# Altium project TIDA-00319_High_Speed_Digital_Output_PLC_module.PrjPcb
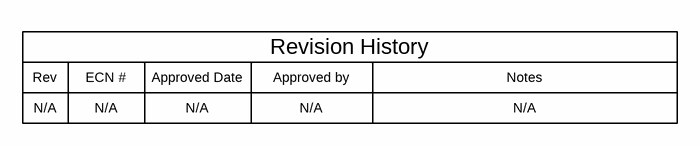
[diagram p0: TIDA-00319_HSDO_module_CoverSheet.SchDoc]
TID: TIDA-00319; TechSupport: http://www.ti.com/support; SCH_Rev: E1; PRJ_Title: High Speed Digital Output Module for PLC; PRJ_Number: TIDA-00319; PRJ_Engineer: Ahmed Noeman; PRJ_Customer: Public Release; PCB_Rev: E1; PCB_Layout: Ahmed Noeman; CopyrightYear: 2016
6 sheets, 93 parts. Net scope: global (net labels, ports and power ports of the same name join across sheets).
Board file: TIDA-00319_HSDO_module.PcbDoc
Sheets:
  TIDA-00319_HSDO_module_CoverSheet.SchDoc
  TIDA-00319_HSDO_module_Hardware.SchDoc
  TIDA-00319_HSDO_module_BBB_connector.SchDoc
  TIDA-00319_HSDO_module_power.SchDoc
  TIDA-00319_HSDO_module_isolation.SchDoc
  TIDA-00319_HSDO_module_singout.SchDoc

## Sheet TIDA-00319_HSDO_module_CoverSheet.SchDoc
size 431 x 279 mm; Date: Not shown in title block; ApprovedBy: Not shown in title block; CheckedBy: Not shown in title block; Author: Not shown in title block; CompanyName: Not shown in title block; DrawnBy: Ahmed Noeman; Engineer: Ahmed Noeman; Organization: Not shown in title block; Address1: Not shown in title block; Address2: Not shown in title block; Address3: Not shown in title block; Address4: Not shown in title block; DocumentNumber: 1; Revision: Use project parameter SCH_Rev; SheetNumber: 1; SheetTotal: 3; PageSetup: Record=PageOptions¦CenterHorizontal=True¦CenterVertical=True¦PrintScale=1.00¦XCorrection=1.00¦YCorrection=1.00¦PrintKind=0¦BorderSize=5000000¦LeftOffset=0¦BottomOffset=0¦Orientation=2¦PaperLength=1000¦PaperWidth=1000¦Scale=100¦PaperSource=15¦PrintQuality=600¦MediaType=1¦DitherType=10¦PaperKind=Letter¦PrintScaleMode=1

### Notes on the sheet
- Rev
- N/A
- ECN #
- Approved Date
- Approved by
- Revision History
- Notes

## Sheet TIDA-00319_HSDO_module_Hardware.SchDoc
size 431 x 279 mm; Date: Not shown in title block; ApprovedBy: Not shown in title block; CheckedBy: Not shown in title block; Author: Not shown in title block; CompanyName: Not shown in title block; DrawnBy: Ahmed Noeman; Engineer: Ahmed Noeman; Organization: Not shown in title block; Address1: Not shown in title block; Address2: Not shown in title block; Address3: Not shown in title block; Address4: Not shown in title block; DocumentNumber: 1; Revision: Use project parameter SCH_Rev; SheetNumber: 2; SheetTotal: 3; PageSetup: Record=PageOptions¦CenterHorizontal=True¦CenterVertical=True¦PrintScale=1.00¦XCorrection=1.00¦YCorrection=1.00¦PrintKind=0¦BorderSize=5000000¦LeftOffset=0¦BottomOffset=0¦Orientation=2¦PaperLength=1000¦PaperWidth=1000¦Scale=100¦PaperSource=15¦PrintQuality=600¦MediaType=1¦DitherType=10¦PaperKind=Letter¦PrintScaleMode=1
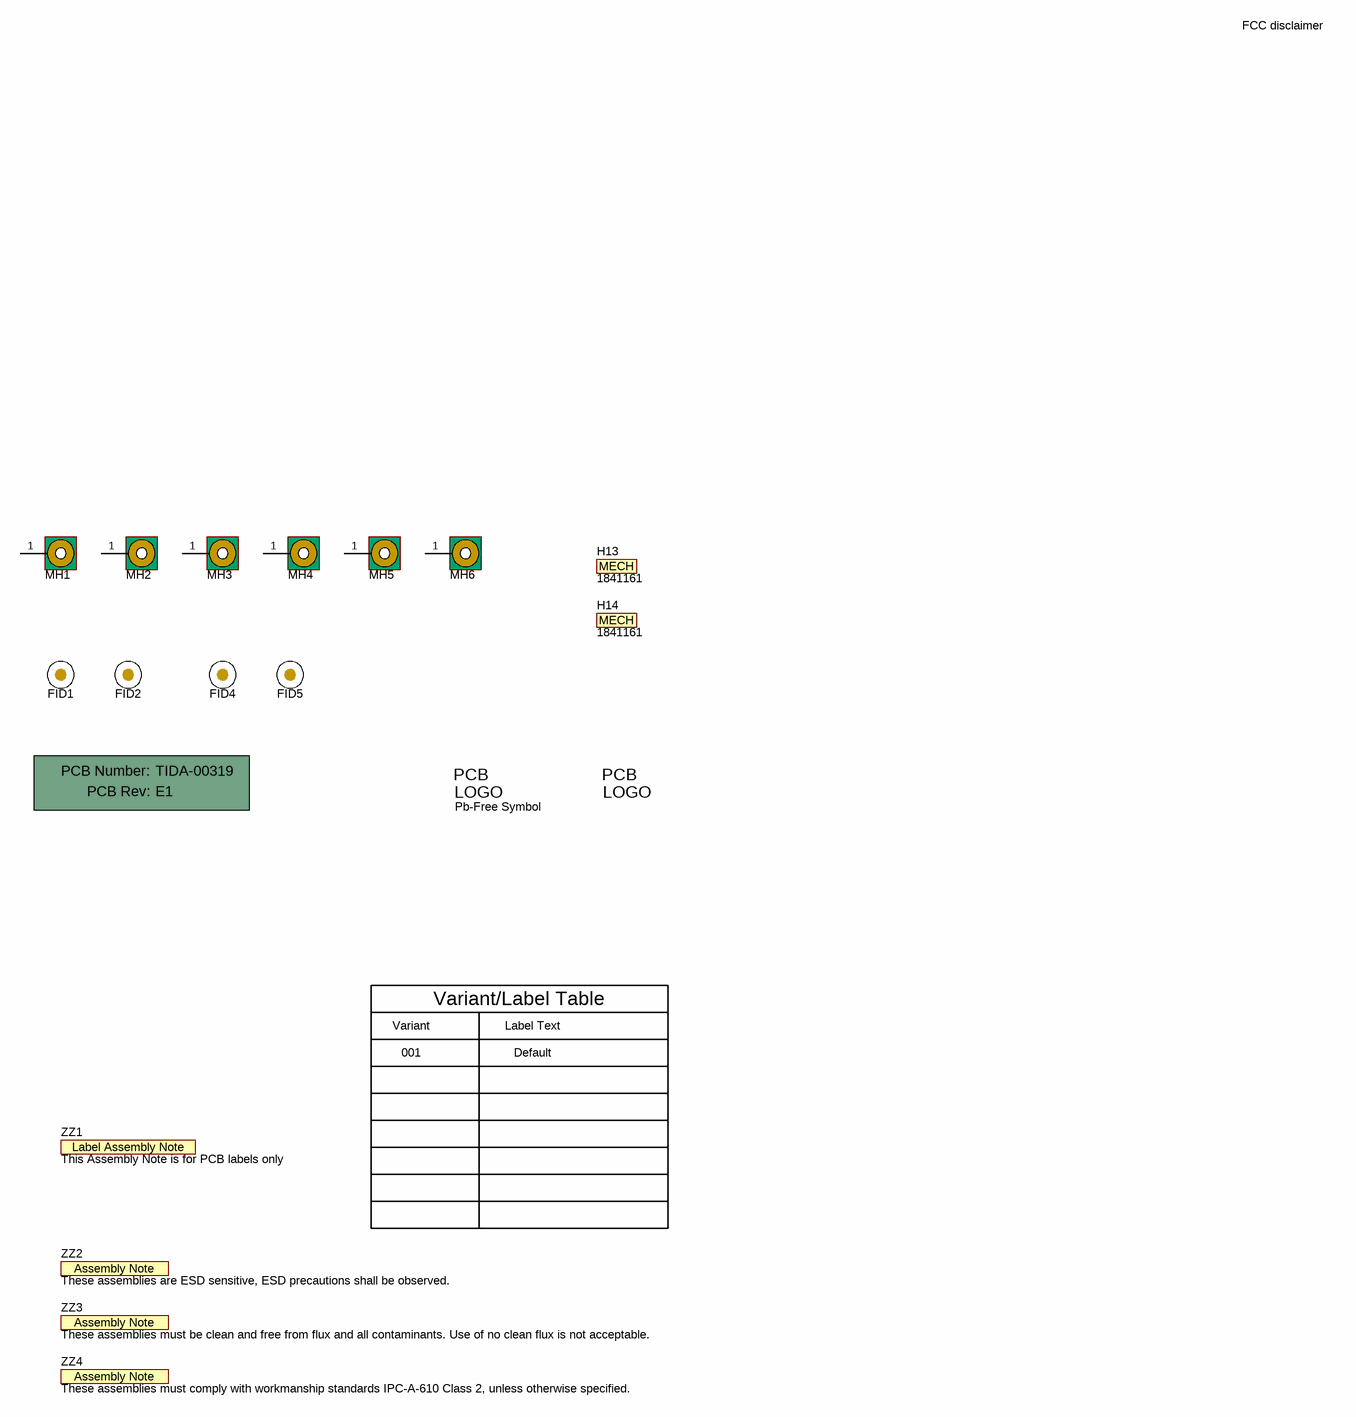
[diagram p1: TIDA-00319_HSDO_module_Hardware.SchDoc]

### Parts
!PCB1  Printed Circuit Board  (value not drawn)  (mechanical)
FID1  Fiducial  [Fiducial10-20]  (value not drawn)
FID2  Fiducial  [Fiducial10-20]  (value not drawn)
FID4  Fiducial  [Fiducial10-20]  (value not drawn)
FID5  Fiducial  [Fiducial10-20]  (value not drawn)
H13  1841161  (mechanical)
H14  1841161  (mechanical)
Logo2  Pb-Free Symbol  [Pb-Free_Overlay_Small]  (no BOM)
Logo3  FCC disclaimer  [FCC_disclaimer_stacked]  (no BOM)
MH1  MTG_Pads  [MTGP_4-40_PanHead]  (value not drawn)  (no BOM)
MH2  MTG_Pads  [MTGP_4-40_PanHead]  (value not drawn)  (no BOM)
MH3  MTG_Pads  [MTGP_4-40_PanHead]  (value not drawn)  (no BOM)
MH4  MTG_Pads  [MTGP_4-40_PanHead]  (value not drawn)  (no BOM)
MH5  MTG_Pads  [MTGP_4-40_PanHead]  (value not drawn)  (no BOM)
MH6  MTG_Pads  [MTGP_4-40_PanHead]  (value not drawn)  (no BOM)
ZZ1  This Assembly Note is for PCB labels only  [AssemblyNoteLabel]  (no BOM)
ZZ2  These assemblies are ESD sensitive, ESD precautions shall be observed.  [AssemblyNote]  (no BOM)
ZZ3  These assemblies must be clean and free from flux and all contaminants. Use of no clean flux is not acceptable.  [AssemblyNote]  (no BOM)
ZZ4  These assemblies must comply with workmanship standards IPC-A-610 Class 2, unless otherwise specified.  [AssemblyNote]  (no BOM)

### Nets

Not connected (* = marked no-connect by the designer): MH1 1; MH2 1; MH3 1; MH4 1; MH5 1; MH6 1

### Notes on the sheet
- Variant
- Variant/Label Table
- Label Text
- 001
- Default

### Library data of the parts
!PCB1 = PCB: Manufacturer: Any; PartNumber: TIDA-00319; SymbolCreator: a0412235
FID1 FID2 FID4 FID5 = Fiducial: Fiducial mark.  There is nothing to buy or mount.; SymbolCreator: codlsc
H13 H14 = 1841161: Fiber optics - MC 1,5/10-LWL 1,5-3,5 for Phoenix connectors; Manufacturer: Phoenix Contact; SymbolCreator: codlsc; CompType: Filber Optics
Logo2 = Pb-Free: SymbolCreator: a0412235
Logo3 = FCC_disclaimer: SymbolCreator: a0412235
MH1-MH6 = Mounting Hole (Imperial) with Pads: PCB Mounting Hole; Manufacturer: Any; SymbolCreator: a0412235
ZZ1 = AssemblyNoteLabel: SymbolCreator: a0412235
ZZ2-ZZ4 = AssemblyNote: SymbolCreator: codlsc

## Sheet TIDA-00319_HSDO_module_BBB_connector.SchDoc
size 431 x 279 mm; Date: Not shown in title block; ApprovedBy: Not shown in title block; CheckedBy: Not shown in title block; Author: Not shown in title block; CompanyName: Not shown in title block; Engineer: Not shown in title block; Organization: Not shown in title block; Address1: Not shown in title block; Address2: Not shown in title block; Address3: Not shown in title block; Address4: Not shown in title block; DocumentNumber: 1; Revision: Use project parameter SCH_Rev; SheetNumber: 3; SheetTotal: 3; PageSetup: Record=PageOptions¦CenterHorizontal=True¦CenterVertical=True¦PrintScale=1.00¦XCorrection=1.00¦YCorrection=1.00¦PrintKind=0¦BorderSize=5000000¦LeftOffset=0¦BottomOffset=0¦Orientation=2¦PaperLength=1000¦PaperWidth=1000¦Scale=100¦PaperSource=15¦PrintQuality=600¦MediaType=1¦DitherType=10¦PaperKind=Letter¦PrintScaleMode=1
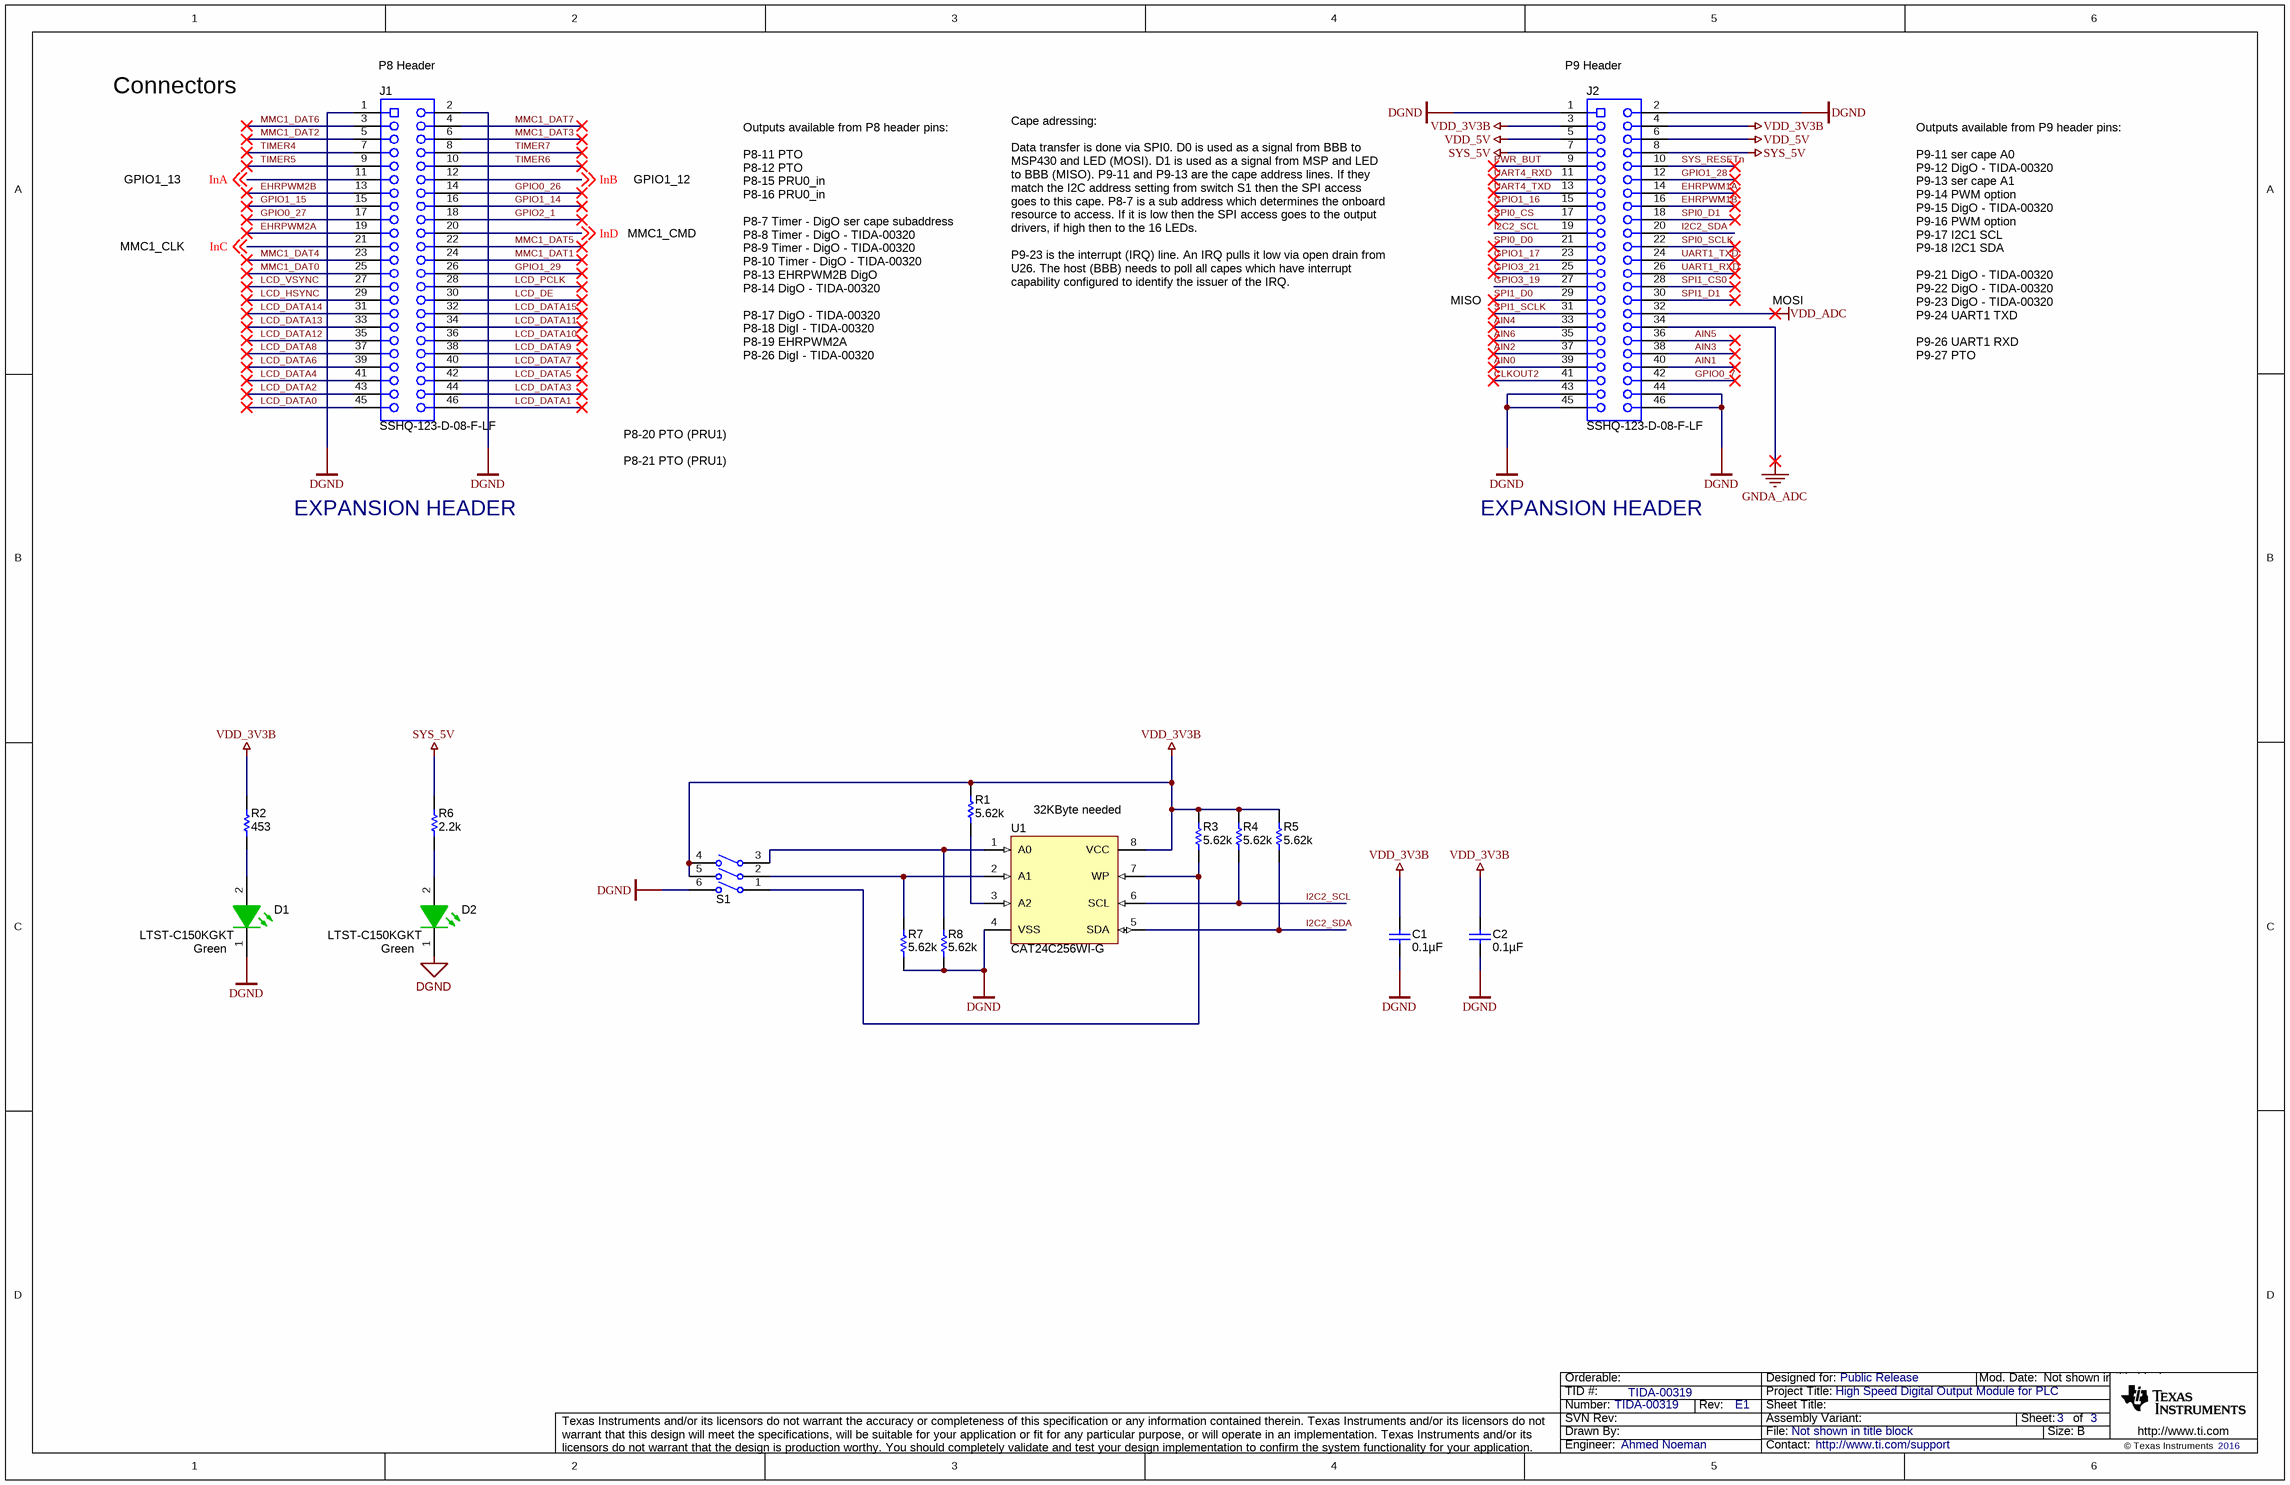
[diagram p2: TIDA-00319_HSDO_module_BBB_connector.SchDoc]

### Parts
C1  ValueDisplayed: 0.1µF  [0603]  (hidden comment: GRM188R71C104KA01D)
C2  ValueDisplayed: 0.1µF  [0603]  (hidden comment: GRM188R71C104KA01D)
D1  LTST-C150KGKT  value Green  [LTST-C150_1206_Green]
D2  LTST-C150KGKT  value Green  [LTST-C150_1206_Green]
J1  SSHQ-123-D-08-F-LF  [Major_BBB_SSHQ-123-D-08]
J2  SSHQ-123-D-08-F-LF  [Major_BBB_SSHQ-123-D-08]
R1  ValueDisplayed: 5.62k  [0603]  (hidden comment: CRCW06035K62FKEA)
R2  ValueDisplayed: 453  [0603]  (hidden comment: CRCW0603453RFKEA)
R3  ValueDisplayed: 5.62k  [0603]  (hidden comment: CRCW06035K62FKEA)
R4  ValueDisplayed: 5.62k  [0603]  (hidden comment: CRCW06035K62FKEA)
R5  ValueDisplayed: 5.62k  [0603]  (hidden comment: CRCW06035K62FKEA)
R6  ValueDisplayed: 2.2k  [0603]  (hidden comment: RC0603JR-072K2L)
R7  ValueDisplayed: 5.62k  [0603]  (hidden comment: CRCW06035K62FKEA)
R8  ValueDisplayed: 5.62k  [0603]  (hidden comment: CRCW06035K62FKEA)
S1  219-3MST  [SW_219-3MST]  (value not drawn)
U1  CAT24C256WI-G  [SOIC-8]

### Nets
DGND: C1.2 C2.2 D1.1(K) D2.1(K) J1.1 J1.2 J2.1 J2.2 J2.43 J2.44 J2.45 J2.46 R7.1 R8.1 S1.6(B1) U1.4(VSS)
GNDA_ADC: J2.34
SYS_5V: J2.7 J2.8 R6.2
VDD_3V3B: C1.1 C2.1 J2.3 J2.4 R1.2 R2.2 R3.2 R4.2 R5.2 S1.4(B3) S1.5(B2) U1.8(VCC)
VDD_5V: J2.5 J2.6
VDD_ADC: J2.32
AIN0: J2.39
AIN1: J2.40
AIN2: J2.37
AIN3: J2.38
AIN4: J2.33
AIN5: J2.36
AIN6: J2.35
CLKOUT2: J2.41
EHRPWM1A: J2.14
EHRPWM1B: J2.16
EHRPWM2A: J1.19
EHRPWM2B: J1.13
GPIO0_7: J2.42
GPIO0_26: J1.14
GPIO0_27: J1.17
GPIO1_14: J1.16
GPIO1_15: J1.15
GPIO1_16: J2.15
GPIO1_17: J2.23
GPIO1_28: J2.12
GPIO1_29: J1.26
GPIO2_1: J1.18
GPIO3_19: J2.27
GPIO3_21: J2.25
I2C2_SCL: J2.19 R4.1 U1.6(SCL)
I2C2_SDA: J2.20 R5.1 U1.5(SDA)
InA: J1.11 ; off-sheet InA
InB: J1.12 ; off-sheet InB
InC: J1.21 ; off-sheet InC
InD: J1.20 ; off-sheet InD
LCD_DATA0: J1.45
LCD_DATA1: J1.46
LCD_DATA2: J1.43
LCD_DATA3: J1.44
LCD_DATA4: J1.41
LCD_DATA5: J1.42
LCD_DATA6: J1.39
LCD_DATA7: J1.40
LCD_DATA8: J1.37
LCD_DATA9: J1.38
LCD_DATA10: J1.36
LCD_DATA11: J1.34
LCD_DATA12: J1.35
LCD_DATA13: J1.33
LCD_DATA14: J1.31
LCD_DATA15: J1.32
LCD_DE: J1.30
LCD_HSYNC: J1.29
LCD_PCLK: J1.28
LCD_VSYNC: J1.27
MMC1_DAT0: J1.25
MMC1_DAT1: J1.24
MMC1_DAT2: J1.5
MMC1_DAT3: J1.6
MMC1_DAT4: J1.23
MMC1_DAT5: J1.22
MMC1_DAT6: J1.3
MMC1_DAT7: J1.4
PWR_BUT: J2.9
SPI0_CS: J2.17
SPI0_D0: J2.21
SPI0_D1: J2.18
SPI0_SCLK: J2.22
SPI1_CS0: J2.28
SPI1_D0: J2.29
SPI1_D1: J2.30
SPI1_SCLK: J2.31
SYS_RESETn: J2.10
TIMER4: J1.7
TIMER5: J1.9
TIMER6: J1.10
TIMER7: J1.8
UART1_RXD: J2.26
UART1_TXD: J2.24
UART4_RXD: J2.11
UART4_TXD: J2.13
NetD1_2: D1.2(A) R2.1
NetD2_2: D2.2(A) R6.1
NetR1_1: R1.1 U1.3(A2)
NetR3_1: R3.1 S1.1(A1) U1.7(WP)
NetR7_2: R7.2 S1.2(A2) U1.2(A1)
NetR8_2: R8.2 S1.3(A3) U1.1(A0)

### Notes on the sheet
- Connectors
- (near J1) P8 Header
- (near J2) P9 Header
- GPIO1_13
- MMC1_CMD
- GPIO1_12
- MMC1_CLK
- Cape adressing:
  Data transfer is done via SPI0. D0 is used as a signal from BBB to MSP430 and LED (MOSI). D1 is used as a signal from MSP and LED to BBB (MISO). P9-11 and P9-13 are the cape address lines. If they match the I2C address setting from switch S1 then the SPI access goes to this cape. P8-7 is a sub address which determines the onboard resource to access. If it is low then the SPI access goes to the output drivers, if high then to the 16 LEDs.
  P9-23 is the interrupt (IRQ) line. An IRQ pulls it low via open drain from U26. The host (BBB) needs to poll all capes which have interrupt capability configured to identify the issuer of the IRQ.
- MISO
- MOSI
- Outputs available from P8 header pins:
  P8-11 PTO
  P8-12 PTO
  P8-15 PRU0_in
  P8-16 PRU0_in
  P8-7 Timer - DigO ser cape subaddress
  P8-8 Timer - DigO - TIDA-00320
  P8-9 Timer - DigO - TIDA-00320
  P8-10 Timer - DigO - TIDA-00320
  P8-13 EHRPWM2B DigO
  P8-14 DigO - TIDA-00320
  P8-17 DigO - TIDA-00320
  P8-18 DigI - TIDA-00320
  P8-19 EHRPWM2A
  P8-26 DigI - TIDA-00320
- Outputs available from P9 header pins:
  P9-11 ser cape A0
  P9-12 DigO - TIDA-00320
  P9-13 ser cape A1
  P9-14 PWM option
  P9-15 DigO - TIDA-00320
  P9-16 PWM option
  P9-17 I2C1 SCL
  P9-18 I2C1 SDA
  P9-21 DigO - TIDA-00320
  P9-22 DigO - TIDA-00320
  P9-23 DigO - TIDA-00320
  P9-24 UART1 TXD
  P9-26 UART1 RXD
  P9-27 PTO
  P9-41 PTO
- P8-20 PTO (PRU1)
- P8-21 PTO (PRU1)
- EXPANSION HEADER
- (near U1) 32KByte needed

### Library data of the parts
C1 C2 = GRM188R71C104KA01D: CAP, CERM, 0.1 µF, 16 V, +/- 10%, X7R, 0603; Manufacturer: MuRata; Polarized: N; CompType: Capacitor; Value: 0.1uF; U/M: EA; Cap_F: 0.0000001; Tolerance_%: 10; Value1: Unknown; VDC_V: 16; Value2: 16V; TaMin_C: -55; TaMax_C: 125
D1 D2 = LTST-C150KGKT: LED, Green, SMD; Manufacturer: LiteOn; SymbolCreator: Altium; Type: AlInGaP; Vf_V: 2; Value2: 2V; Io_A: 0.03; Vr_V: 5; Tjmax_C: 85; Value1: W; Angle: 130; U/M: EA
J1 J2 = SSHQ-123-D-08-F-LF: Female Connector, 2.54mm, 23x2, TH; Manufacturer: Major League Electronics; SymbolCreator: Altium; CompType: Receptacle; U/M: EA
R1 R3-R5 R7 R8 = CRCW06035K62FKEA: RES, 5.62 k, 1%, 0.1 W, 0603; Manufacturer: Vishay-Dale; CompType: Resistor; Value: 5.62k; Res_ohm: 5620; Value_Code: 5k62; Tolerance_%: 1; Power_W: 0.1; Value2: 0.1W; VDC_V: 75; TempCo: 100 ppm/C; EIA_Code: E96; U/M: EA
R2 = CRCW0603453RFKEA: RES, 453, 1%, 0.1 W, 0603; Manufacturer: Vishay-Dale; CompType: Resistor; Value: 453; Value_Code: 453R; Tolerance_%: 1; Power_W: 0.1; Value2: 0.1W; VDC_V: 75; TempCo: 100 ppm/C; EIA_Code: E96; U/M: EA
R6 = RC0603JR-072K2L: RES, 2.2 k, 5%, 0.1 W, 0603; Manufacturer: Yageo America; CompType: Resistor; Value: 2.2k; Res_ohm: 2200; Value_Code: 2k20; Tolerance_%: 5; Power_W: 0.1; Value2: 0.1W; VDC_V: 50; TempCo: 100 ppm/C; SizeArea_mm2: 1.28; SizeX_mm: 1.6; SizeY_mm: 0.8; SizeZ_mm: 1; EIA_Code: E24; U/M: EA; AEC Category: Q200
S1 = 219-3MST: Switch, SPST, Slide, Off-On, 3 Pos, 0.1A, 20V, SMD; Manufacturer: CTS Electrocomponents; VDC_V: 20; PositionCount: 3; CurrentRating_mA: 100
U1 = CAT24C256WI-G: 256 kb I2C CMOS Serial EEPROM, SOIC-8; Manufacturer: ON Semiconductor; SymbolCreator: a0411947

## Sheet TIDA-00319_HSDO_module_power.SchDoc
size 431 x 279 mm; Date: Not shown in title block; ApprovedBy: Not shown in title block; CheckedBy: Not shown in title block; Author: Not shown in title block; CompanyName: Not shown in title block; DrawnBy: Ahmed Noeman; Engineer: Ahmed Noeman; Organization: Not shown in title block; Address1: Not shown in title block; Address2: Not shown in title block; Address3: Not shown in title block; Address4: Not shown in title block; DocumentNumber: 1; Revision: Use project parameter SCH_Rev; SheetNumber: 4; SheetTotal: 3; PageSetup: Record=PageOptions¦CenterHorizontal=True¦CenterVertical=True¦PrintScale=1.00¦XCorrection=1.00¦YCorrection=1.00¦PrintKind=0¦BorderSize=5000000¦LeftOffset=0¦BottomOffset=0¦Orientation=2¦PaperLength=1000¦PaperWidth=1000¦Scale=100¦PaperSource=15¦PrintQuality=600¦MediaType=1¦DitherType=10¦PaperKind=Letter¦PrintScaleMode=1
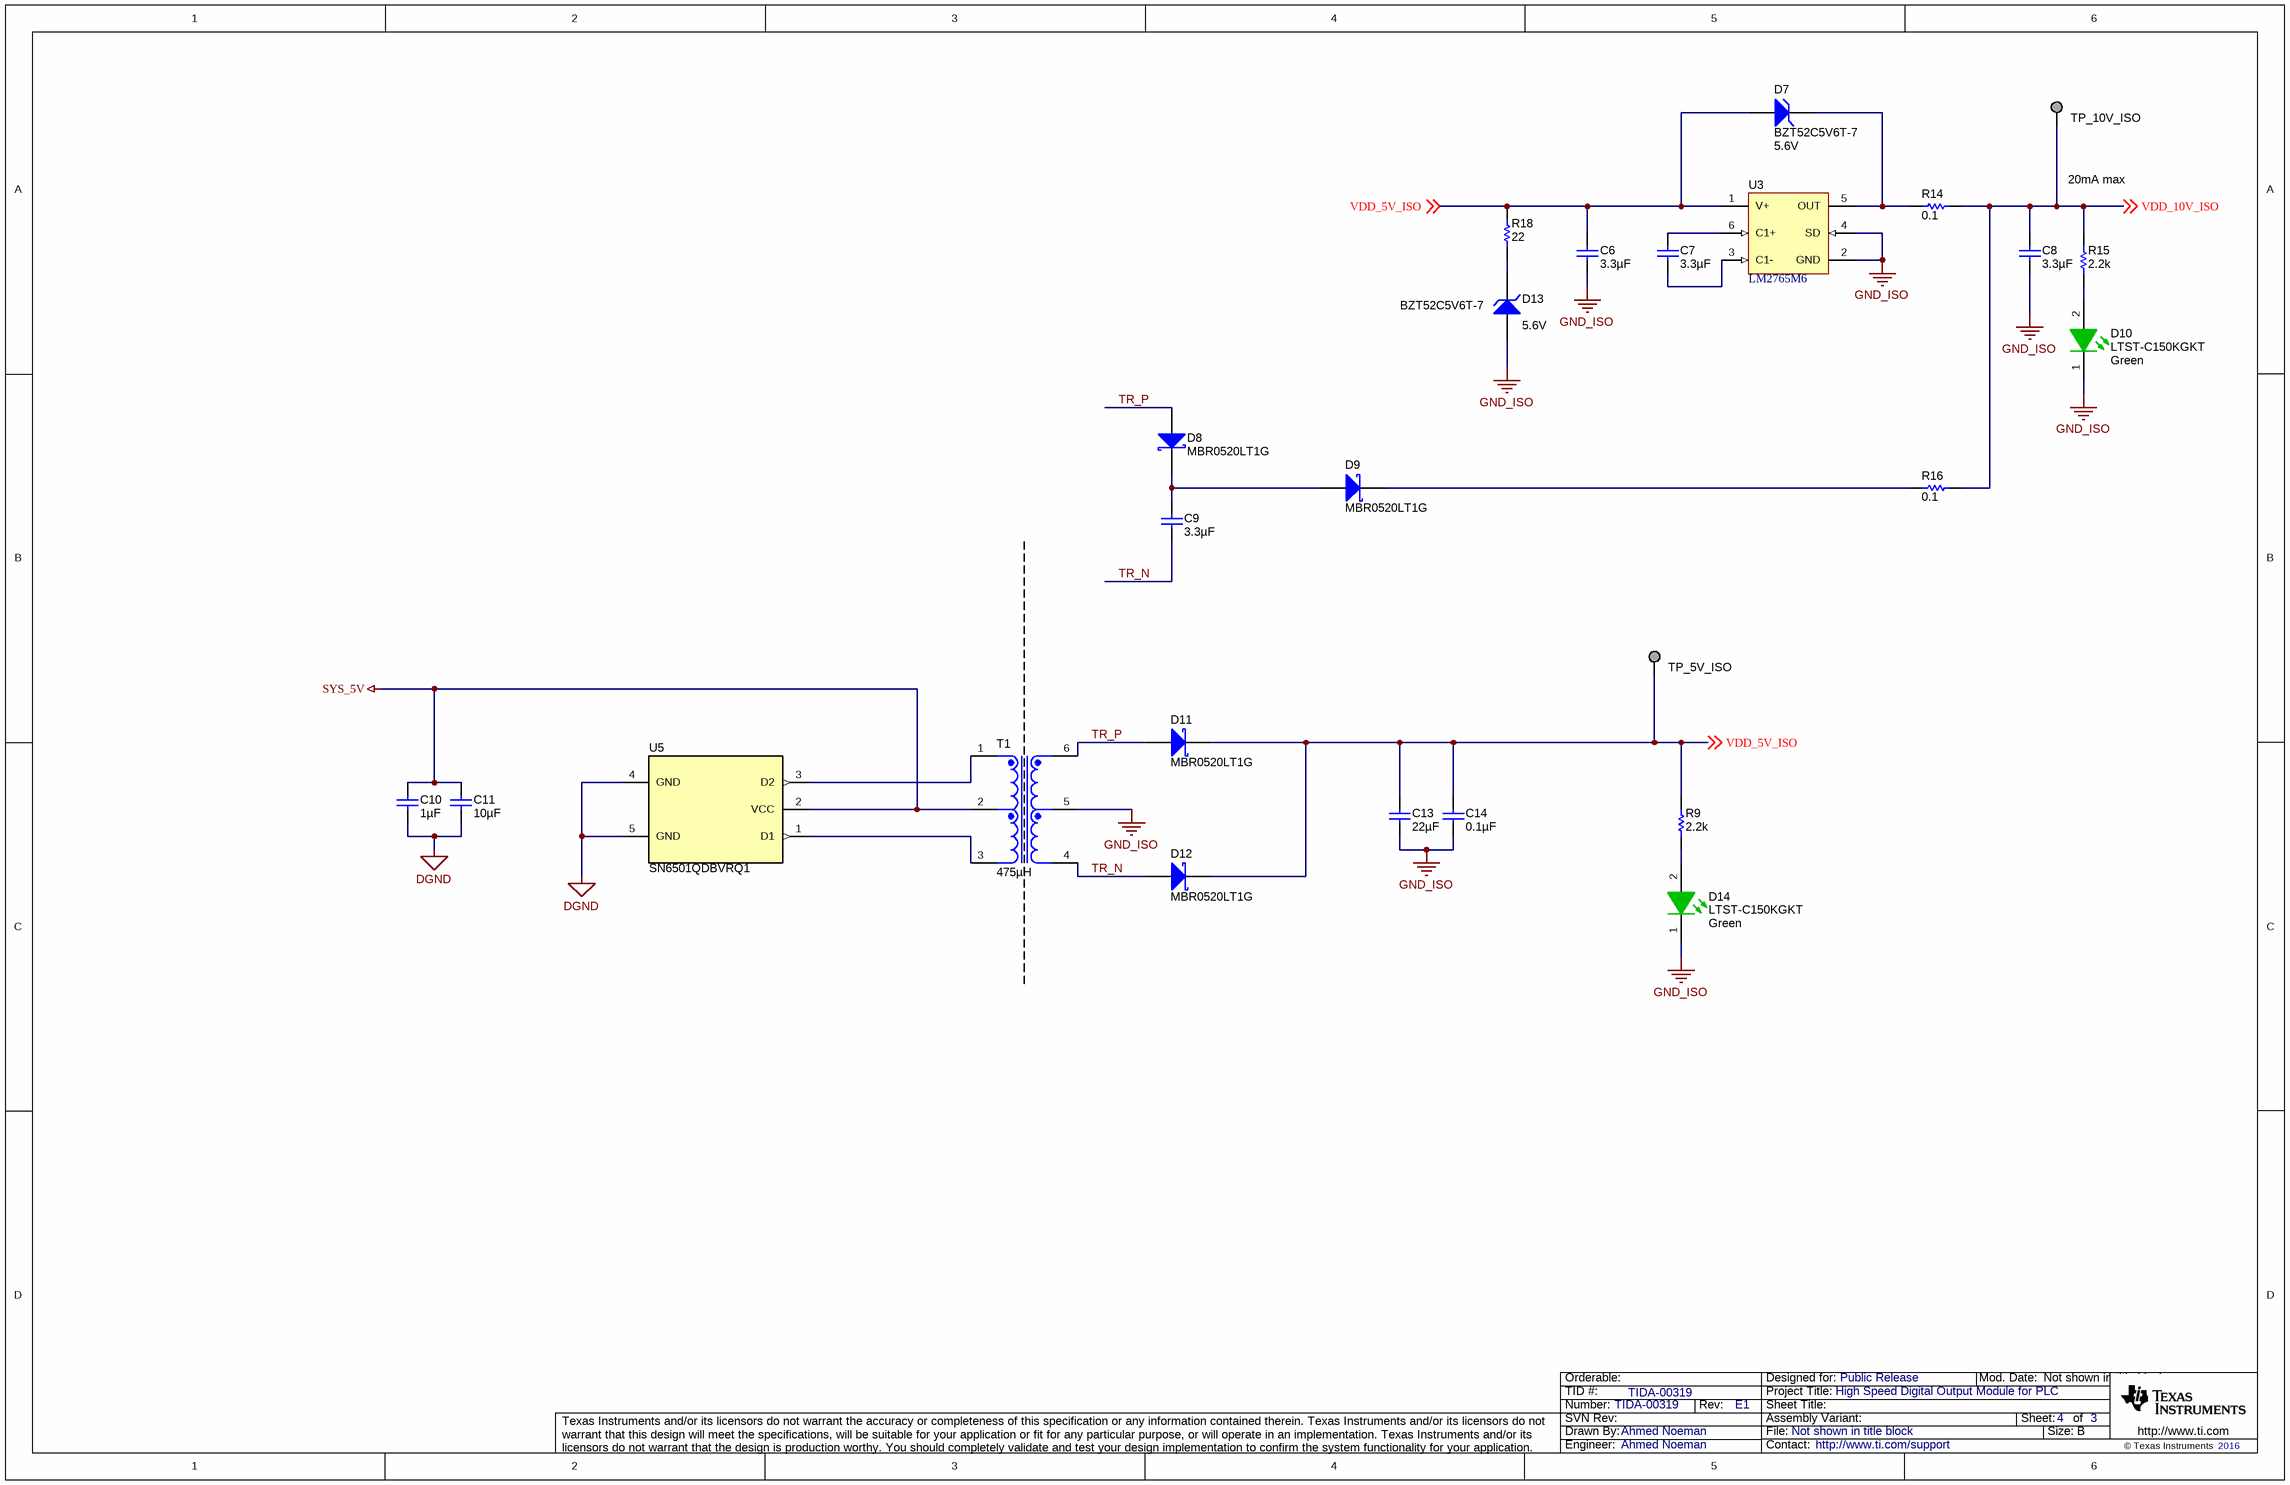
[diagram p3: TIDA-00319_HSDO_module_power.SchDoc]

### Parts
C6  ValueDisplayed: 3.3µF  [0805_HV]  (hidden comment: GRM21BR71C335KA99L)
C7  ValueDisplayed: 3.3µF  [0805_HV]  (hidden comment: GRM21BR71C335KA99L)
C8  ValueDisplayed: 3.3µF  [0805_HV]  (hidden comment: GRM21BR71C335KA99L)
C9  ValueDisplayed: 3.3µF  [0603]  (hidden comment: C1608X5R1E335K080AC)
C10  ValueDisplayed: 1µF  [0603]  (hidden comment: C1608X7R1C105K080AC)
C11  ValueDisplayed: 10µF  [0603]  (hidden comment: C1608X5R1A106M080AC)
C13  ValueDisplayed: 22µF  [0805_HV]  (hidden comment: C2012X5R1C226K125AC)
C14  ValueDisplayed: 0.1µF  [0603]  (hidden comment: GRM188R71C104KA01D)
D7  BZT52C5V6T-7  value 5.6V  [SOD-523]
D8  MBR0520LT1G  [SOD-123]
D9  MBR0520LT1G  [SOD-123]
D10  LTST-C150KGKT  value Green  [LTST-C150_1206_Green]
D11  MBR0520LT1G  [SOD-123]
D12  MBR0520LT1G  [SOD-123]
D13  BZT52C5V6T-7  value 5.6V  [SOD-523]
D14  LTST-C150KGKT  value Green  [LTST-C150_1206_Green]
R9  ValueDisplayed: 2.2k  [0603]  (hidden comment: RC0603JR-072K2L)
R14  ValueDisplayed: 0.1  [0603]  (hidden comment: ERJ-L03KF10CV)
R15  ValueDisplayed: 2.2k  [0603]  (hidden comment: RC0603JR-072K2L)
R16  ValueDisplayed: 0.1  [0603]  (hidden comment: ERJ-L03KF10CV)
R18  ValueDisplayed: 22  [0603]  (hidden comment: CRCW060322R0JNEA)
T1  ValueDisplayed: 475µH  [Wurth_760390012]  (hidden comment: 760390012)
TP_5V_ISO  TESTPOINT  [TESTPOINT]  (value not drawn)  (no BOM)
TP_10V_ISO  TESTPOINT  [TESTPOINT]  (value not drawn)  (no BOM)
U3  LM2765M6  [MF06A_N]
U5  SN6501QDBVRQ1  [DBV0005A_N]

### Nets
DGND: C10.2 C11.2 U5.4(GND) U5.5(GND)
GND_ISO: C6.2 C8.2 C13.2 C14.2 D10.1(K) D13.2(A) D14.1(K) T1.5 U3.2(GND) U3.4(SD)
SYS_5V: C10.1 C11.1 T1.2 U5.2(VCC)
TR_N: C9.2 D12.2(A) T1.4
TR_P: D8.2(A) D11.2(A) T1.6
VDD_5V_ISO: C6.1 C13.1 C14.1 D7.2(A) D11.1(K) D12.1(K) R9.2 R18.2 TP_5V_ISO.1 U3.1(V+) ; off-sheet VDD_5V_ISO
VDD_10V_ISO: C8.1 R14.2 R15.2 R16.2 TP_10V_ISO.1 ; off-sheet VDD_10V_ISO
NetC7_1: C7.1 U3.6(C1+)
NetC7_2: C7.2 U3.3(C1-)
NetC9_1: C9.1 D8.1(K) D9.2(A)
NetD7_1: D7.1(K) R14.1 U3.5(OUT)
NetD9_1: D9.1(K) R16.1
NetD10_2: D10.2(A) R15.1
NetD13_1: D13.1(K) R18.1
NetD14_2: D14.2(A) R9.1
NetT1_1: T1.1 U5.3(D2)
NetT1_3: T1.3 U5.1(D1)

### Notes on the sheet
- 20mA max

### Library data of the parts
C6-C8 = GRM21BR71C335KA99L: CAP, CERM, 3.3 µF, 16 V, +/- 10%, X7R, 0805; Manufacturer: MuRata; Polarized: N; CompType: Capacitor; Value: 3.3uF; U/M: EA; Cap_F: 0.0000033; Tolerance_%: 10; Value1: Unknown; VDC_V: 16; Value2: 16V; TaMin_C: -55; TaMax_C: 125; Cap_Case: 0805; AEC Category: Q200
C9 = C1608X5R1E335K080AC: CAP, CERM, 3.3 µF, 25 V, +/- 10%, X5R, 0603; Manufacturer: TDK; Polarized: N; CompType: Capacitor; Value: 3.3uF; U/M: EA; Cap_F: 0.0000033; Tolerance_%: 10; Value1: Unknown; VDC_V: 25; Value2: 25V; TaMin_C: -55; TaMax_C: 85; AEC Category: Q200
C10 = C1608X7R1C105K080AC: CAP, CERM, 1 µF, 16 V, +/- 10%, X7R, 0603; Manufacturer: TDK; Polarized: N; CompType: Capacitor; Value: 1uF; U/M: EA; Cap_F: 0.000001; Tolerance_%: 10; ESR_ohm: 0.0057; Value1: 0.0057 ohm; VDC_V: 16; Value2: 16V; TaMin_C: -55; TaMax_C: 125; AEC Category: Q200
C11 = C1608X5R1A106M080AC: CAP, CERM, 10 µF, 10 V, +/- 20%, X5R, 0603; Manufacturer: TDK; Polarized: N; CompType: Capacitor; Value: 10uF; U/M: EA; Cap_F: 0.00001; Tolerance_%: 20; ESR_ohm: 0.0078; Value1: 0.0078 ohm; VDC_V: 10; Value2: 10V; IRMS_A: 1.85; TaMin_C: -55; TaMax_C: 85; AEC Category: Q200
C13 = C2012X5R1C226K125AC: CAP, CERM, 22 µF, 16 V, +/- 10%, X5R, 0805; Manufacturer: TDK; Polarized: N; CompType: Capacitor; Value: 22uF; U/M: EA; Cap_F: 0.000022; Tolerance_%: 10; Value1: Unknown; VDC_V: 16; Value2: 16V; TaMin_C: -55; TaMax_C: 85; Cap_Case: 0805; AEC Category: Q200
C14 = GRM188R71C104KA01D: CAP, CERM, 0.1 µF, 16 V, +/- 10%, X7R, 0603; Manufacturer: MuRata; Polarized: N; CompType: Capacitor; Value: 0.1uF; U/M: EA; Cap_F: 0.0000001; Tolerance_%: 10; Value1: Unknown; VDC_V: 16; Value2: 16V; TaMin_C: -55; TaMax_C: 125; AEC Category: Q200
D7 D13 = BZT52C5V6T-7: Diode, Zener, 5.6 V, 300 mW, SOD-523; Manufacturer: Diodes Inc.; SymbolCreator: a0412235; U/M: EA; Power_W: 0.3; Vz_V: 5.6; Value1: 0.3W; RJA_CperW: 417; AEC Category: Q101
D8 D9 D11 D12 = MBR0520LT1G: Diode, Schottky, 20 V, 0.5 A, SOD-123; Manufacturer: ON Semiconductor; U/M: EA; Vf_V: 0.385; Value: 20V; Value1: 0.5A; Value2: 0.385V; Io_A: 0.5; Vr_V: 20; TJmax_C: 125; RJC_CperW: 150; AEC Category: Q101
D10 D14 = LTST-C150KGKT: as D1 on sheet TIDA-00319_HSDO_module_BBB_connector
R9 R15 = RC0603JR-072K2L: as R6 on sheet TIDA-00319_HSDO_module_BBB_connector
R14 R16 = ERJ-L03KF10CV: RES, 0.1, 1%, 0.1 W, 0603; Manufacturer: Panasonic; CompType: Resistor; Value: 0.1; Value_Code: R100; Tolerance_%: 1; Value2: 0.1W; TempCo: 200 ppm/C; SizeArea_mm2: 1.28; SizeX_mm: 1.6; SizeY_mm: 0.8; EIA_Code: E96; U/M: EA; AEC Category: Q200
R18 = CRCW060322R0JNEA: RES, 22, 5%, 0.1 W, 0603; Manufacturer: Vishay-Dale; CompType: Resistor; Value: 22; Value_Code: 22R0; Tolerance_%: 5; Power_W: 0.1; Value2: 0.1W; VDC_V: 75; TempCo: 200 ppm/C; SizeArea_mm2: 1.28; SizeX_mm: 1.6; SizeY_mm: 0.8; SizeZ_mm: 1; EIA_Code: E24; U/M: EA; AEC Category: Q200
T1 = 760390012: Transformer, 475 uH, SMT; Manufacturer: Wurth Elektronik; SymbolCreator: Altium; Value: 475uH; Lp: 475; DCR_ohm: 0.31; Ns1toNp: 1.1; Rs1: 0.33; SizeAreaWB_mm2: 105.1965; SizeArea_mm2: 67.6365; SizeX_mm: 10.05; SizeY_mm: 6.73; SizeZ_mm: 4.19
TP_5V_ISO TP_10V_ISO = TESTPOINT: TEST POINT.  No entry in BOM.
U3 = LM2765M6: Switched Capacitor Voltage Converter, 6-pin SOT-23; Manufacturer: Texas Instruments; PackageTopMarking: S15B*XTT; CompType: Switch Caps
U5 = SN6501QDBVRQ1: Transformer Driver for Isolated Power Supplies, DBV0005A; Manufacturer: Texas Instruments; SymbolCreator: a0411947; SizeArea_mm2: 8.12; SizeAreaWB_mm2: 14.82; SizeX_mm: 2.8; SizeY_mm: 2.9; SizeZ_mm: 1.45; CompType: IC; U/M: EA

## Sheet TIDA-00319_HSDO_module_isolation.SchDoc
size 431 x 279 mm; Date: Not shown in title block; ApprovedBy: Not shown in title block; CheckedBy: Not shown in title block; Author: Not shown in title block; CompanyName: Not shown in title block; DrawnBy: Ahmed Noeman; Engineer: Ahmed Noeman; Organization: Not shown in title block; Address1: Not shown in title block; Address2: Not shown in title block; Address3: Not shown in title block; Address4: Not shown in title block; DocumentNumber: 1; Revision: Use project parameter SCH_Rev; SheetNumber: 5; SheetTotal: 3; PageSetup: Record=PageOptions¦CenterHorizontal=True¦CenterVertical=True¦PrintScale=1.00¦XCorrection=1.00¦YCorrection=1.00¦PrintKind=0¦BorderSize=5000000¦LeftOffset=0¦BottomOffset=0¦Orientation=2¦PaperLength=1000¦PaperWidth=1000¦Scale=100¦PaperSource=15¦PrintQuality=600¦MediaType=1¦DitherType=10¦PaperKind=Letter¦PrintScaleMode=1
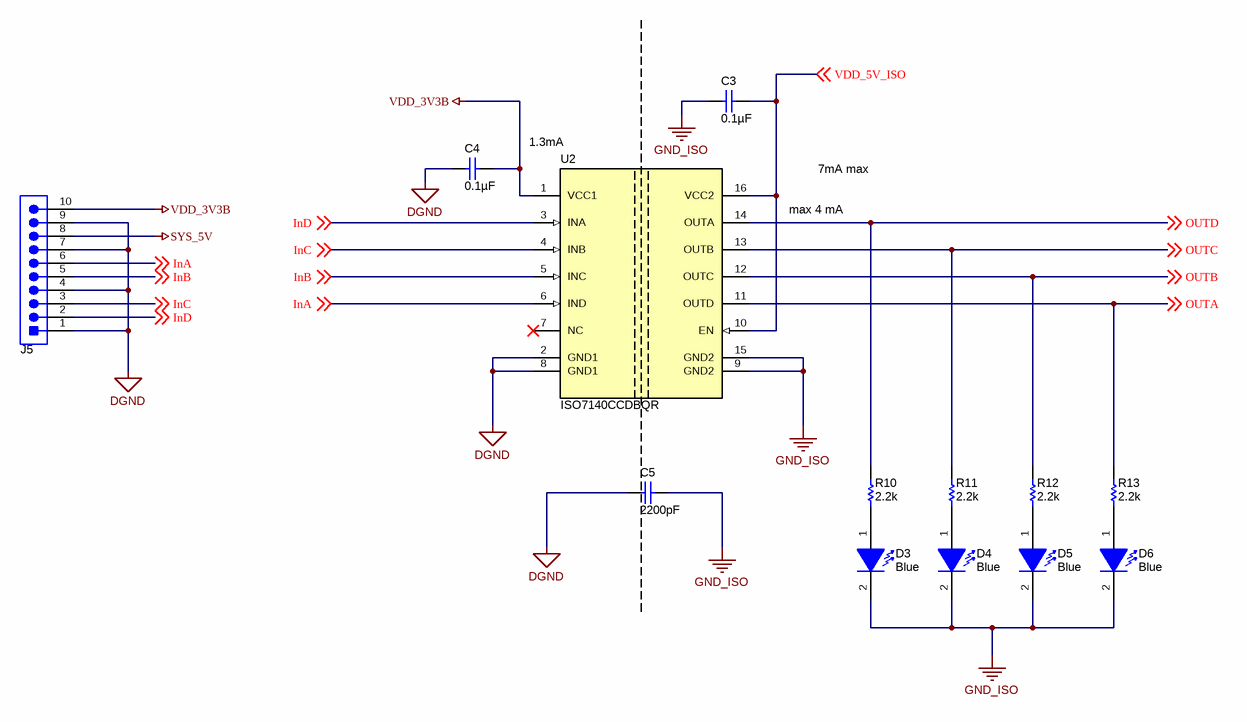
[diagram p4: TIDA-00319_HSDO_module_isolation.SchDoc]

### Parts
C3  ValueDisplayed: 0.1µF  [0603]  (hidden comment: 06033C104KAT2A)
C4  ValueDisplayed: 0.1µF  [0603]  (hidden comment: 06033C104KAT2A)
C5  ValueDisplayed: 2200pF  [1812_254]  (hidden comment: 1812HC222KAT1A)
D3  value Blue  [LB Q39G_BLUE]  (hidden comment: LB Q39G-L2N2-35-1)
D4  value Blue  [LB Q39G_BLUE]  (hidden comment: LB Q39G-L2N2-35-1)
D5  value Blue  [LB Q39G_BLUE]  (hidden comment: LB Q39G-L2N2-35-1)
D6  value Blue  [LB Q39G_BLUE]  (hidden comment: LB Q39G-L2N2-35-1)
J5  800-10-010-10-001000  [Mill-Max_800-10-010-10-001000]  (value not drawn)
R10  ValueDisplayed: 2.2k  [0603]  (hidden comment: RC0603JR-072K2L)
R11  ValueDisplayed: 2.2k  [0603]  (hidden comment: RC0603JR-072K2L)
R12  ValueDisplayed: 2.2k  [0603]  (hidden comment: RC0603JR-072K2L)
R13  ValueDisplayed: 2.2k  [0603]  (hidden comment: RC0603JR-072K2L)
U2  ISO7140CCDBQR  [DBQ0016A_N]

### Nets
DGND: C4.1 C5.2 J5.1 J5.4 J5.7 J5.9 U2.2(GND1) U2.8(GND1)
GND_ISO: C3.1 C5.1 D3.2(K) D4.2(K) D5.2(K) D6.2(K) U2.9(GND2) U2.15(GND2)
SYS_5V: J5.8
VDD_3V3B: C4.2 J5.10 U2.1(VCC1)
InA: J5.6 U2.6(IND) ; off-sheet InA
InB: J5.5 U2.5(INC) ; off-sheet InB
InC: J5.3 U2.4(INB) ; off-sheet InC
InD: J5.2 U2.3(INA) ; off-sheet InD
OUTA: R13.2 U2.11(OUTD) ; off-sheet OUTA
OUTB: R12.2 U2.12(OUTC) ; off-sheet OUTB
OUTC: R11.2 U2.13(OUTB) ; off-sheet OUTC
OUTD: R10.2 U2.14(OUTA) ; off-sheet OUTD
VDD_5V_ISO: C3.2 U2.10(EN) U2.16(VCC2) ; off-sheet VDD_5V_ISO
NetD3_1: D3.1(A) R10.1
NetD4_1: D4.1(A) R11.1
NetD5_1: D5.1(A) R12.1
NetD6_1: D6.1(A) R13.1

Not connected (* = marked no-connect by the designer): U2 7(NC)*

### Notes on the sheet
- 1.3mA
- 7mA max
- max 4 mA

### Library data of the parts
C3 C4 = 06033C104KAT2A: CAP, CERM, 0.1 µF, 25 V, +/- 10%, X7R, 0603; Manufacturer: AVX; Polarized: N; CompType: Capacitor; Value: 0.1uF; U/M: EA; Cap_F: 0.0000001; Tolerance_%: 10; ESR_ohm: 0.05; Value1: 0.05 ohm; VDC_V: 25; Value2: 25V; TaMin_C: -55; TaMax_C: 125; AEC Category: Q200
C5 = 1812HC222KAT1A: CAP, CERM, 2200 pF, 3000 V, +/- 10%, X7R, 1812; Manufacturer: AVX; Polarized: N; CompType: Capacitor; Value: 2200pF; U/M: EA; Cap_F: 0.0000000022; Tolerance_%: 10; Value1: Unknown; VDC_V: 3000; Value2: 3000V; TaMin_C: -55; TaMax_C: 125; Cap_Case: 1812; AEC Category: Q200
D3-D6 = LB Q39G-L2N2-35-1: LED, Blue, SMD; Manufacturer: OSRAM; Vf_V: 2.85; Value2: 2.85V; Io_A: 0.15; Tjmax_C: 95; Value1: W; U/M: EA
J5 = 800-10-010-10-001000: Header, 100mil, 10x1, TH; Manufacturer: Mill-Max; SymbolCreator: a0412235
R10-R13 = RC0603JR-072K2L: as R6 on sheet TIDA-00319_HSDO_module_BBB_connector
U2 = ISO7140CCDBQR: 4242-VPK Small-Footprint and Low-Power Quad Channels Digital Isolators, DBQ0016A; Manufacturer: Texas Instruments; SymbolCreator: a0799628; SizeX_mm: 6; SizeY_mm: 10; SizeZ_mm: 1.75; CompType: IC; U/M: EA

## Sheet TIDA-00319_HSDO_module_singout.SchDoc
size 431 x 279 mm; Date: Not shown in title block; ApprovedBy: Not shown in title block; CheckedBy: Not shown in title block; Author: Not shown in title block; CompanyName: Not shown in title block; DrawnBy: Ahmed Noeman; Engineer: Ahmed Noeman; Organization: Not shown in title block; Address1: Not shown in title block; Address2: Not shown in title block; Address3: Not shown in title block; Address4: Not shown in title block; DocumentNumber: 1; Revision: Use project parameter SCH_Rev; SheetNumber: 2; SheetTotal: 3; PageSetup: Record=PageOptions¦CenterHorizontal=True¦CenterVertical=True¦PrintScale=1.00¦XCorrection=1.00¦YCorrection=1.00¦PrintKind=0¦BorderSize=5000000¦LeftOffset=0¦BottomOffset=0¦Orientation=2¦PaperLength=1000¦PaperWidth=1000¦Scale=100¦PaperSource=15¦PrintQuality=600¦MediaType=1¦DitherType=10¦PaperKind=Letter¦PrintScaleMode=1
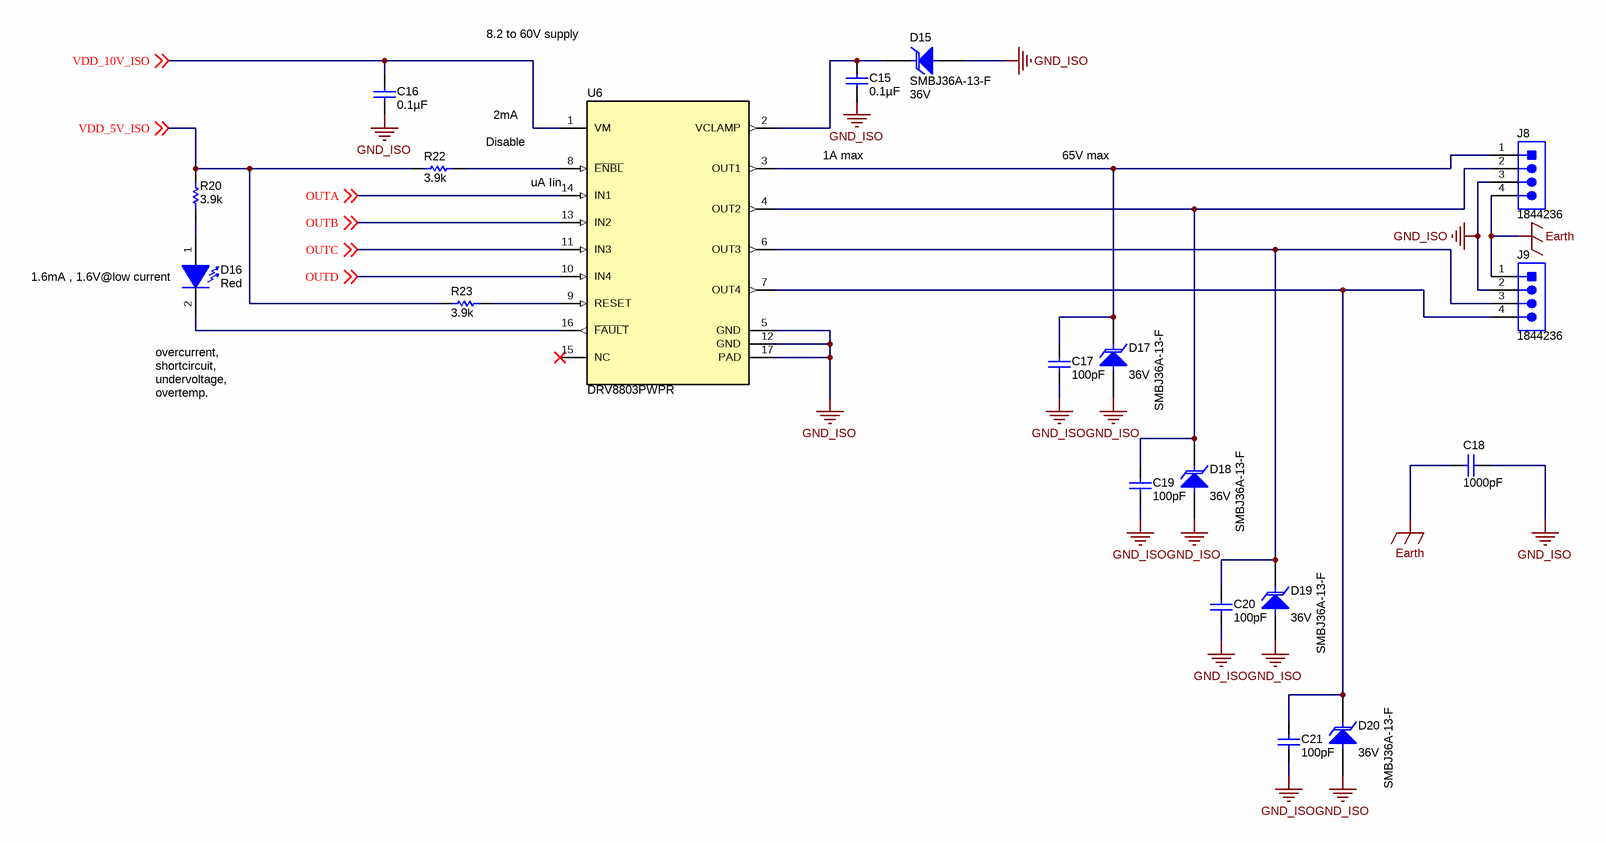
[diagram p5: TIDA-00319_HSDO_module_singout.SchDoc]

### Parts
C15  ValueDisplayed: 0.1µF  [0603]  (hidden comment: 06033C104KAT2A)
C16  ValueDisplayed: 0.1µF  [0603]  (hidden comment: 06033C104KAT2A)
C17  ValueDisplayed: 100pF  [0603]  (hidden comment: CGA3E2NP01H101J080AA)
C18  ValueDisplayed: 1000pF  [1206_190]  (hidden comment: 202R18W102KV4E)
C19  ValueDisplayed: 100pF  [0603]  (hidden comment: CGA3E2NP01H101J080AA)
C20  ValueDisplayed: 100pF  [0603]  (hidden comment: CGA3E2NP01H101J080AA)
C21  ValueDisplayed: 100pF  [0603]  (hidden comment: CGA3E2NP01H101J080AA)
D15  SMBJ36A-13-F  value 36V  [SMB]
D16  value Red  [LED_LTST-C190_Red]  (hidden comment: LTST-C190CKT)
D17  SMBJ36A-13-F  value 36V  [SMB]
D18  SMBJ36A-13-F  value 36V  [SMB]
D19  SMBJ36A-13-F  value 36V  [SMB]
D20  SMBJ36A-13-F  value 36V  [SMB]
J8  1844236  [Phoenix_1844236]
J9  1844236  [Phoenix_1844236]
R20  ValueDisplayed: 3.9k  [0603]  (hidden comment: RC0603JR-073K9L)
R22  ValueDisplayed: 3.9k  [0603]  (hidden comment: RC0603JR-073K9L)
R23  ValueDisplayed: 3.9k  [0603]  (hidden comment: RC0603JR-073K9L)
U6  DRV8803PWPR  [PWP0016D_N]

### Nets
Earth: C18.2 J8.4 J9.1
GND_ISO: C15.2 C16.2 C17.2 C18.1 C19.2 C20.2 C21.2 D15.2(A) D17.2(A) D18.2(A) D19.2(A) D20.2(A) J8.3 J9.2 U6.5(GND) U6.12(GND) U6.17(PAD)
OUTA: U6.14(IN1) ; off-sheet OUTA
OUTB: U6.13(IN2) ; off-sheet OUTB
OUTC: U6.11(IN3) ; off-sheet OUTC
OUTD: U6.10(IN4) ; off-sheet OUTD
VDD_5V_ISO: R20.1 R22.2 R23.2 ; off-sheet VDD_5V_ISO
VDD_10V_ISO: C16.1 U6.1(VM) ; off-sheet VDD_10V_ISO
NetC15_1: C15.1 D15.1(K) U6.2(VCLAMP)
NetC17_1: C17.1 D17.1(K) J8.1 U6.3(OUT1)
NetC19_1: C19.1 D18.1(K) J8.2 U6.4(OUT2)
NetC20_1: C20.1 D19.1(K) J9.3 U6.6(OUT3)
NetC21_1: C21.1 D20.1(K) J9.4 U6.7(OUT4)
NetD16_1: D16.1(A) R20.2
NetD16_2: D16.2(K) U6.16(~{FAULT})
NetR22_1: R22.1 U6.8(~{ENBL})
NetR23_1: R23.1 U6.9(RESET)

Not connected (* = marked no-connect by the designer): U6 15(NC)*

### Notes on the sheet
- 8.2 to 60V supply
- 2mA
- Disable
- 1A max
- 65V max
- (near U6) uA Iin
- (near D16) 1.6mA , 1.6V@low current
- overcurrent, shortcircuit, undervoltage, overtemp.

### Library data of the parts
C15 C16 = 06033C104KAT2A: as C3 on sheet TIDA-00319_HSDO_module_isolation
C17 C19-C21 = CGA3E2NP01H101J080AA: CAP, CERM, 100 pF, 50 V, +/- 5%, C0G/NP0, AEC-Q200 Grade 0, 0603; Manufacturer: TDK; Polarized: N; CompType: Capacitor; Value: 100pF; U/M: EA; Cap_F: 0.0000000001; Tolerance_%: 5; Value1: Unknown; VDC_V: 50; Value2: 50V; TaMin_C: -55; TaMax_C: 150; AEC Category: Q200; AEC Qualified: Y; AEC Grade: 0
C18 = 202R18W102KV4E: CAP, CERM, 1000 pF, 2000 V, +/- 10%, X7R, 1206_190; Manufacturer: Johanson Technology; Polarized: N; CompType: Capacitor; Value: 1000pF; U/M: EA; Cap_F: 0.000000001; Tolerance_%: 10; Value1: Unknown; VDC_V: 2000; Value2: 2000V; TaMin_C: -55; TaMax_C: 125; Cap_Case: 1206; AEC Category: Q200
D15 D17-D20 = SMBJ36A-13-F: Diode, TVS, Uni, 36 V, 600 W, SMB; Manufacturer: Diodes Inc.; U/M: EA; Power_W: 5; Vr_V: 36; Value1: 5W; SizeAreaWB_mm2: 44.156; SizeArea_mm2: 21.336; SizeX_mm: 5.6; SizeY_mm: 3.81; SizeZ_mm: 2.6; AEC Category: Q101
D16 = LTST-C190CKT: LED, Red, SMD; Manufacturer: Lite-On; Vf_V: 2; Value2: 2V; Io_A: 0.02; Tjmax_C: 85; Power_TotalModule: 0.0625; Value1: 0.0625W; U/M: EA
J8 J9 = 1844236: Terminal Block, 4x1, 3.5mm, Green, R/A, TH; Manufacturer: Phoenix Contact; SymbolCreator: a0412235; CompType: Header; Pitch_mm: 3.5; Gender: Male; Row_Count: 1; Current_A: 8; Voltage_V: 300; Cert_CSA: Y
R20 R22 R23 = RC0603JR-073K9L: RES, 3.9 k, 5%, 0.1 W, 0603; Manufacturer: Yageo America; CompType: Resistor; Value: 3.9k; Res_ohm: 3900; Value_Code: 3k90; Tolerance_%: 5; Power_W: 0.1; Value2: 0.1W; VDC_V: 50; TempCo: 100 ppm/C; SizeArea_mm2: 1.28; SizeX_mm: 1.6; SizeY_mm: 0.8; SizeZ_mm: 1; EIA_Code: E24; U/M: EA; AEC Category: Q200
U6 = DRV8803PWPR: Quad Low-Side Driver IC, PWP0016D; Manufacturer: Texas Instruments; SymbolCreator: Altium; SizeX_mm: 6.4; SizeY_mm: 5; SizeZ_mm: 1.2; CompType: d; U/M: EA

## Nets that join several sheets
DGND: TIDA-00319_HSDO_module_BBB_connector (16 pins), TIDA-00319_HSDO_module_power (C10.2 C11.2 U5.4 U5.5), TIDA-00319_HSDO_module_isolation (8 pins)
GND_ISO: TIDA-00319_HSDO_module_power (10 pins), TIDA-00319_HSDO_module_isolation (8 pins), TIDA-00319_HSDO_module_singout (17 pins)
SYS_5V: TIDA-00319_HSDO_module_BBB_connector (J2.7 J2.8 R6.2), TIDA-00319_HSDO_module_power (C10.1 C11.1 T1.2 U5.2), TIDA-00319_HSDO_module_isolation (J5.8)
VDD_3V3B: TIDA-00319_HSDO_module_BBB_connector (12 pins), TIDA-00319_HSDO_module_isolation (C4.2 J5.10 U2.1)
InA: TIDA-00319_HSDO_module_BBB_connector (J1.11), TIDA-00319_HSDO_module_isolation (J5.6 U2.6)
InB: TIDA-00319_HSDO_module_BBB_connector (J1.12), TIDA-00319_HSDO_module_isolation (J5.5 U2.5)
InC: TIDA-00319_HSDO_module_BBB_connector (J1.21), TIDA-00319_HSDO_module_isolation (J5.3 U2.4)
InD: TIDA-00319_HSDO_module_BBB_connector (J1.20), TIDA-00319_HSDO_module_isolation (J5.2 U2.3)
OUTA: TIDA-00319_HSDO_module_isolation (R13.2 U2.11), TIDA-00319_HSDO_module_singout (U6.14)
OUTB: TIDA-00319_HSDO_module_isolation (R12.2 U2.12), TIDA-00319_HSDO_module_singout (U6.13)
OUTC: TIDA-00319_HSDO_module_isolation (R11.2 U2.13), TIDA-00319_HSDO_module_singout (U6.11)
OUTD: TIDA-00319_HSDO_module_isolation (R10.2 U2.14), TIDA-00319_HSDO_module_singout (U6.10)
VDD_5V_ISO: TIDA-00319_HSDO_module_power (10 pins), TIDA-00319_HSDO_module_isolation (C3.2 U2.10 U2.16), TIDA-00319_HSDO_module_singout (R20.1 R22.2 R23.2)
VDD_10V_ISO: TIDA-00319_HSDO_module_power (5 pins), TIDA-00319_HSDO_module_singout (C16.1 U6.1)

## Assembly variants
001: not fitted C9 D8 D9 R16 R22 R23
